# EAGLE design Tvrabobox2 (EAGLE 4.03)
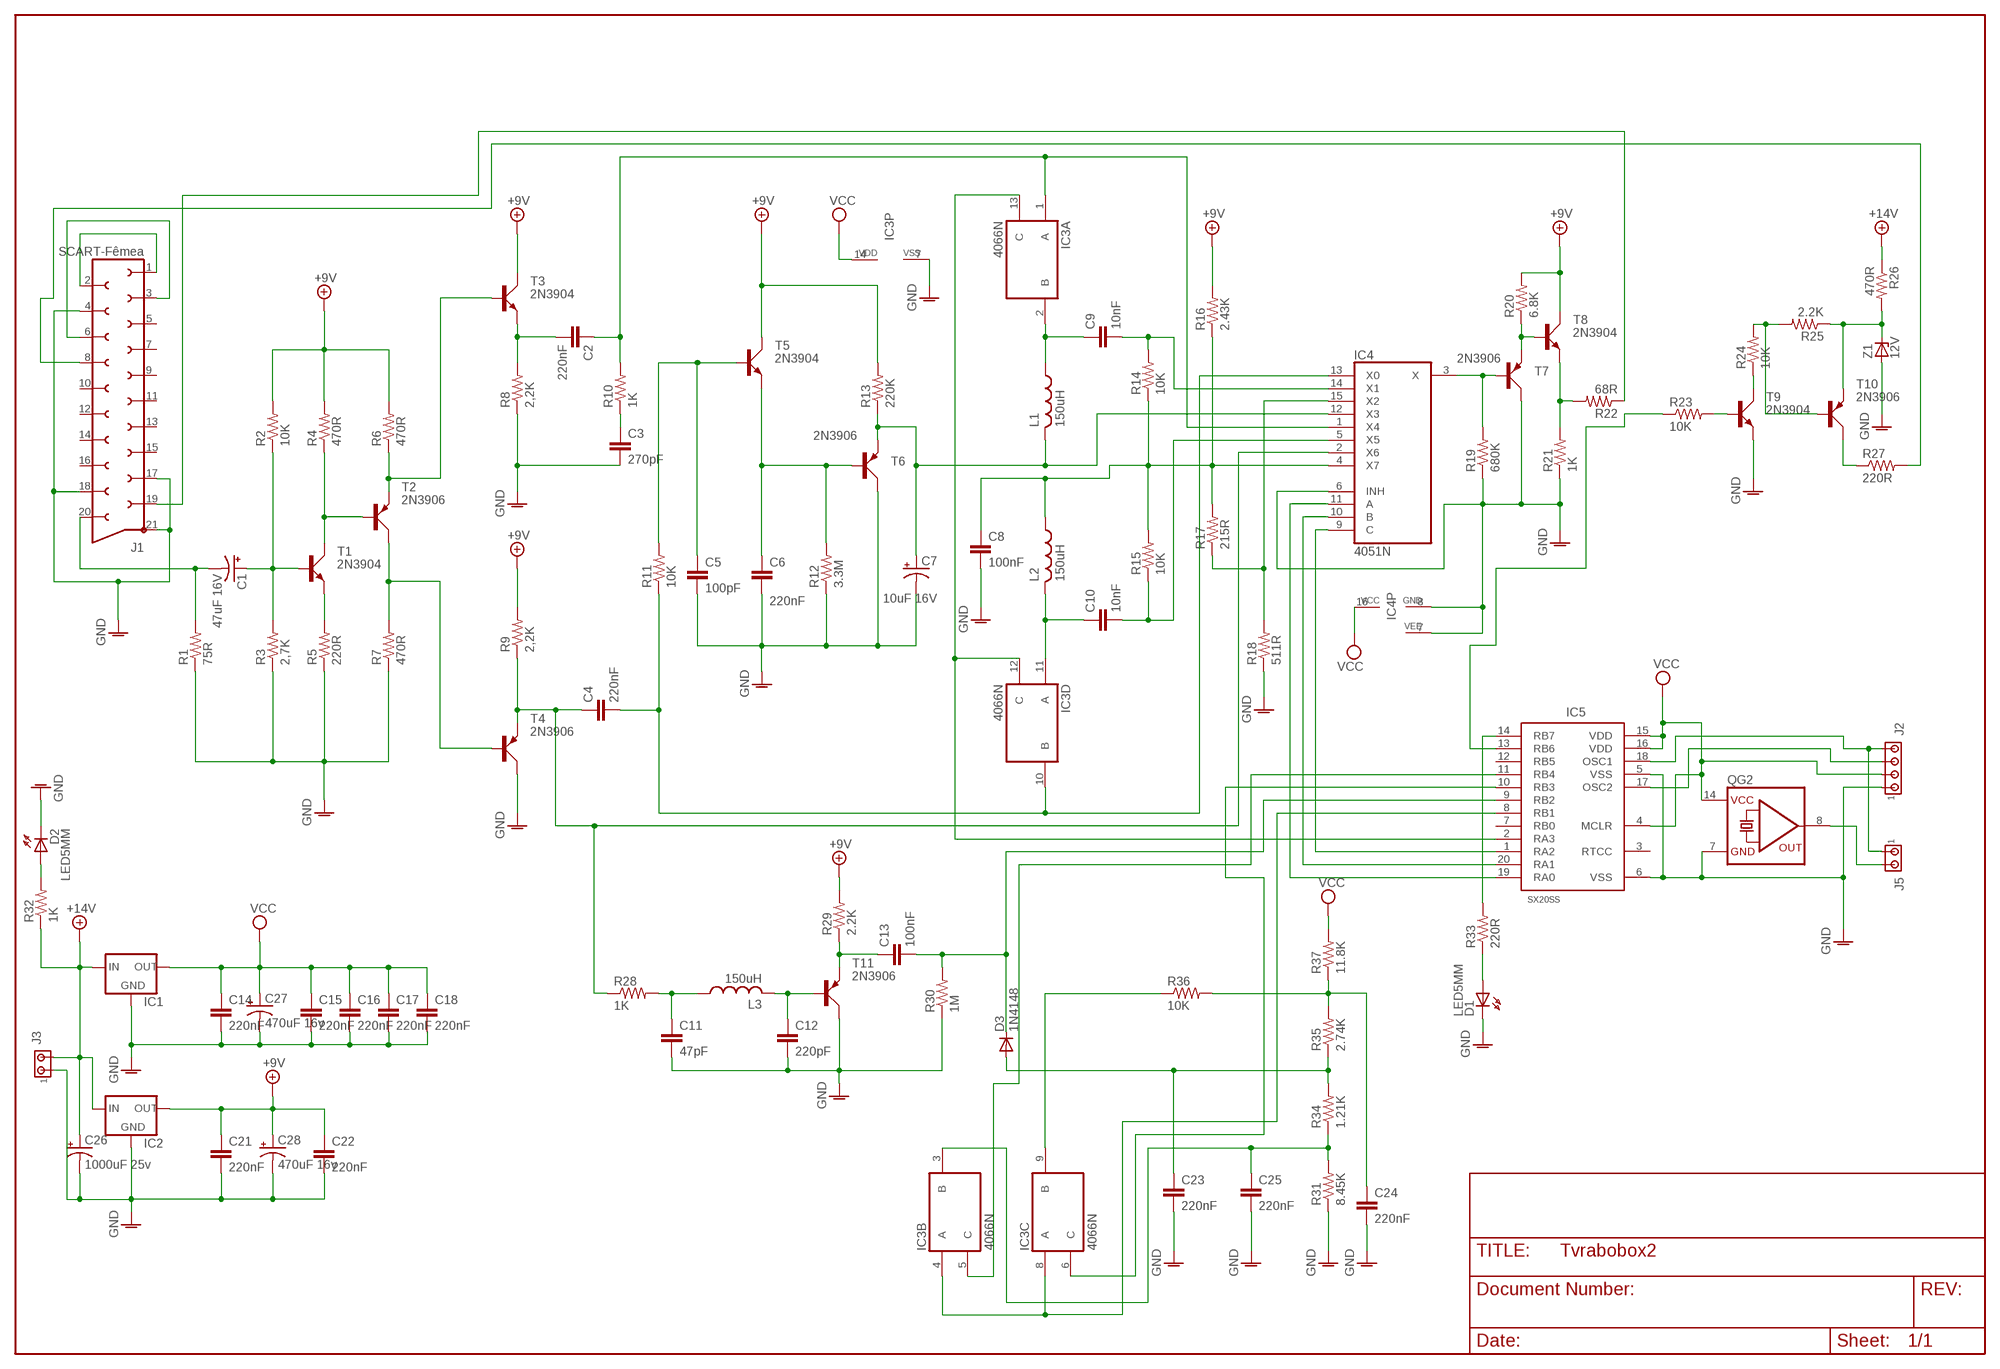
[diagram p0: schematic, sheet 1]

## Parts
C1  47uF 16V  CPOL-USTT2D5  [TT2D5]
C2  220nF  C-EU050-050X075  [C050-050X075]
C3  270pF  C-EU025-025X050  [C025-025X050]
C4  220nF  C-EU050-050X075  [C050-050X075]
C5  100pF  C-EU025-025X050  [C025-025X050]
C6  220nF  C-EU050-050X075  [C050-050X075]
C7  10uF 16V  CPOL-USTT2D5  [TT2D5]
C8  100nF  C-EU025-025X050  [C025-025X050]
C9  10nF  C-EU025-025X050  [C025-025X050]
C10  10nF  C-EU025-025X050  [C025-025X050]
C11  47pF  C-EU025-025X050  [C025-025X050]
C12  220pF  C-EU050-050X075  [C050-050X075]
C13  100nF  C-EU025-025X050  [C025-025X050]
C14  220nF  C-EU050-050X075  [C050-050X075]
C15  220nF  C-EU050-050X075  [C050-050X075]
C16  220nF  C-EU050-050X075  [C050-050X075]
C17  220nF  C-EU050-050X075  [C050-050X075]
C18  220nF  C-EU050-050X075  [C050-050X075]
C21  220nF  C-EU050-050X075  [C050-050X075]
C22  220nF  C-EU050-050X075  [C050-050X075]
C23  220nF  C-EU050-050X075  [C050-050X075]
C24  220nF  C-EU050-050X075  [C050-050X075]
C25  220nF  C-EU050-050X075  [C050-050X075]
C26  1000uF 25v  CPOL-USTT5D10  [TT5D10]
C27  470uF 16v  CPOL-USTT2D7  [TT2D7]
C28  470uF 16v  CPOL-USTT2D7  [TT2D7]
D1  LED5MM  [LED5MM]
D2  LED5MM  [LED5MM]
D3  1N4148  [DO35-10]
IC1  78XXS  [78XXS]
IC2  78XXS  [78XXS]
IC3  4066N  [DIL14]
IC4  4051N  [DIL16]
IC5  SX20AC/SS  [20SSOP]
J1  SCART-Fêmea  SCART-F  [SCART-F]
J2  MTA04-100  [10X04MTA]
J3  MTA02-156  [1X2MTA]
J5  MTA02-100  [10X02MTA]
L1  150uH  L-US0207/10  [0207/10]
L2  150uH  L-US0207/10  [0207/10]
L3  150uH  L-US0207/10  [0207/10]
QG2  QG5860  [DIL14S]
R1  75R  R-US_0207/10  [0207/10]
R2  10K  R-US_0207/10  [0207/10]
R3  2,7K  R-US_0207/10  [0207/10]
R4  470R  R-US_0207/10  [0207/10]
R5  220R  R-US_0207/10  [0207/10]
R6  470R  R-US_0207/10  [0207/10]
R7  470R  R-US_0207/10  [0207/10]
R8  2,2K  R-US_0207/10  [0207/10]
R9  2,2K  R-US_0207/10  [0207/10]
R10  1K  R-US_0207/10  [0207/10]
R11  10K  R-US_0207/10  [0207/10]
R12  3.3M  R-US_0207/10  [0207/10]
R13  220K  R-US_0207/10  [0207/10]
R14  10K  R-US_0207/10  [0207/10]
R15  10K  R-US_0207/10  [0207/10]
R16  2.43K  R-US_0207/10  [0207/10]
R17  215R  R-US_0207/10  [0207/10]
R18  511R  R-US_0207/10  [0207/10]
R19  680K  R-US_0207/10  [0207/10]
R20  6.8K  R-US_0207/10  [0207/10]
R21  1K  R-US_0207/10  [0207/10]
R22  68R  R-US_0207/10  [0207/10]
R23  10K  R-US_0207/10  [0207/10]
R24  10K  R-US_0207/10  [0207/10]
R25  2.2K  R-US_0207/10  [0207/10]
R26  470R  R-US_0207/10  [0207/10]
R27  220R  R-US_0207/10  [0207/10]
R28  1K  R-US_0207/10  [0207/10]
R29  2.2K  R-US_0207/10  [0207/10]
R30  1M  R-US_0207/10  [0207/10]
R31  8.45K  R-US_0207/10  [0207/10]
R32  1K  R-US_0207/10  [0207/10]
R33  220R  R-US_0207/10  [0207/10]
R34  1.21K  R-US_0207/10  [0207/10]
R35  2.74K  R-US_0207/10  [0207/10]
R36  10K  R-US_0207/10  [0207/10]
R37  11.8K  R-US_0207/10  [0207/10]
T1  2N3904  [TO92D]
T2  2N3906  [TO92D]
T3  2N3904  [TO92D]
T4  2N3906  [TO92D]
T5  2N3904  [TO92D]
T6  2N3906  [TO92D]
T7  2N3906  [TO92D]
T8  2N3904  [TO92D]
T9  2N3904  [TO92D]
T10  2N3906  [TO92D]
T11  2N3906  [TO92D]
Z1  12V  BZX55  [DO35Z10]

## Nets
+9V: C21.2 C22.2 C28.+ IC2.OUT R2.2 R4.2 R6.2 R9.2 R13.2 R16.2 R20.2 R29.2 T3.C T5.C T8.C
+14V: C26.+ IC1.IN IC2.IN J3.2 R26.1 R32.1
GNDA: C3.1 C5.1 C6.1 C7.- C8.1 C11.1 C12.1 C14.1 C15.1 C16.1 C17.1 C18.1 C21.1 C22.1 C23.1 C24.1 C25.1 C26.- C27.- C28.- D1.K(C) D2.K(C) IC1.GND IC2.GND IC3.7(P:VSS) IC4.6(INH) IC4.7(VEE) IC4.8(GND) IC5.5(VSS) IC5.6(VSS) J1.4 J1.17 J1.18 J1.21 J2.4 J3.1 QG2.7(GND) R1.1 R3.1 R5.1 R7.1 R8.1 R12.1 R18.1 R19.1 R21.1 R30.1 R31.1 T4.C T6.C T7.C T9.E T11.C Z1.A ; supply symbol labelled GND
N$1: J1.1 J1.2
N$2: J1.3 J1.6
N$3: C4.1 IC3.10(D:B) IC4.13(X0) R11.1
N$4: C3.2 R10.1
N$5: R4.1 T1.C T2.B
N$6: R5.2 T1.E
N$7: C1.+ R2.1 R3.2 T1.B
N$8: C1.- J1.20 R1.2
N$9: C2.1 R8.2 T3.E
N$10: C4.2 IC4.2(X6) R9.1 R28.1 T4.E
N$11: C9.2 IC3.2(A:B) L1.2
N$12: C2.2 IC3.1(A:A) IC4.1(X4) R10.2
N$13: R6.1 T2.E T3.B
N$14: R7.2 T2.C T4.B
N$15: C5.2 R11.2 T5.B
N$16: C6.2 R12.2 T5.E T6.B
N$17: C8.2 IC4.4(X7) L2.2 R14.1 R15.2 R16.1 R17.2
N$18: IC4.15(X2) R17.1 R18.2
N$19: C7.+ IC4.12(X3) L1.1 R13.1 T6.E
N$20: C9.1 IC4.14(X1) R14.2
N$21: IC4.11(A) IC5.19(RA0)
N$22: C10.2 IC3.11(D:A) L2.1
N$23: IC4.10(B) IC5.20(RA1)
N$24: C10.1 IC4.5(X5) R15.1
N$25: IC4.9(C) IC5.1(RA2)
N$26: IC3.12(D:C) IC3.13(A:C) IC5.2(RA3)
N$27: IC4.3(X) R19.2 T7.B
N$28: R20.1 T7.E T8.B
N$29: J1.19 R22.1
N$30: R23.2 T9.B
N$31: R21.2 R22.2 T8.E
N$32: R24.1 T9.C
N$33: R24.2 R25.2 T10.B
N$34: C23.2 D3.A R34.2 R35.1
N$35: R27.1 T10.C
N$36: IC5.13(RB6) R23.1
N$37: J1.8 R27.2
N$38: R25.1 R26.2 T10.E Z1.C
N$39: C24.2 R35.2 R36.2 R37.1
N$41: C25.2 IC3.3(B:B) R31.2 R34.1
N$42: C11.2 L3.2 R28.2
N$43: C12.2 L3.1 T11.B
N$44: C13.2 R29.1 T11.E
N$45: IC3.6(C:C) IC5.10(RB3)
N$46: C13.1 D3.C IC5.9(RB2) R30.2
N$47: D2.A R32.2
N$48: IC3.4(B:A) IC3.8(C:A) IC5.8(RB1)
N$49: IC3.5(B:C) IC5.11(RB4)
N$52: IC5.17(OSC2) J2.2
N$53: IC5.18(OSC1) J2.1 J5.1
N$54: IC3.9(C:B) R36.1
N$55: J5.2 QG2.8(OUT)
N$63: D1.A R33.1
N$64: IC5.14(RB7) R33.2
VCC: C14.2 C15.2 C16.2 C17.2 C18.2 C27.+ IC1.OUT IC3.14(P:VDD) IC4.16(VCC) IC5.4(MCLR) IC5.15(VDD) IC5.16(VDD) J2.3 QG2.14(VCC) R37.2
Unconnected: IC5.3(RTCC) IC5.7(RB0) IC5.12(RB5) J1.5 J1.7 J1.9 J1.10 J1.11 J1.12 J1.13 J1.14 J1.15 J1.16

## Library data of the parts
C1 C7 C26-C28 = rcl:CPOL-US: POLARIZED CAPACITOR, American symbol
C2-C6 C8-C18 C21-C25 = rcl:C-EU: CAPACITOR, European symbol
D1 D2 = led:LED5MM: LED
D3 = diode:1N4148: DIODE
IC1 IC2 = v-reg:78XXS: VOLTAGE REGULATOR
IC3 = 40xx:4066: Quad bilateral ANALOG SWITCH
IC4 = 40xx:4051: 8-channel ANALOG MULTIPLEXER
IC5 = ubicom_v2:SX20AC/SS
J1 = con-hirschmann:SCART-F: TV SCART CONNECTOR
J2 = con-amp:MTA04-100: AMP CONNECTOR
J3 = con-amp:MTA02-156: AMP CONNECTOR
J5 = con-amp:MTA02-100: AMP CONNECTOR
L1-L3 = rcl:L-US: INDUCTOR, American symbol
QG2 = crystal:QG5860: CRYSTAL RESONATOR
R1-R37 = rcl:R-US_: RESISTOR, American symbol
T1 T3 T5 T8 T9 = transistor-small-signal:2N3904: NPN TRANSISTOR
T2 T4 T6 T7 T10 T11 = transistor-small-signal:2N3906: PNP TRANSISTOR
Z1 = diode:BZX55: Z DIODE

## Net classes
0 default: width 0.3 mm

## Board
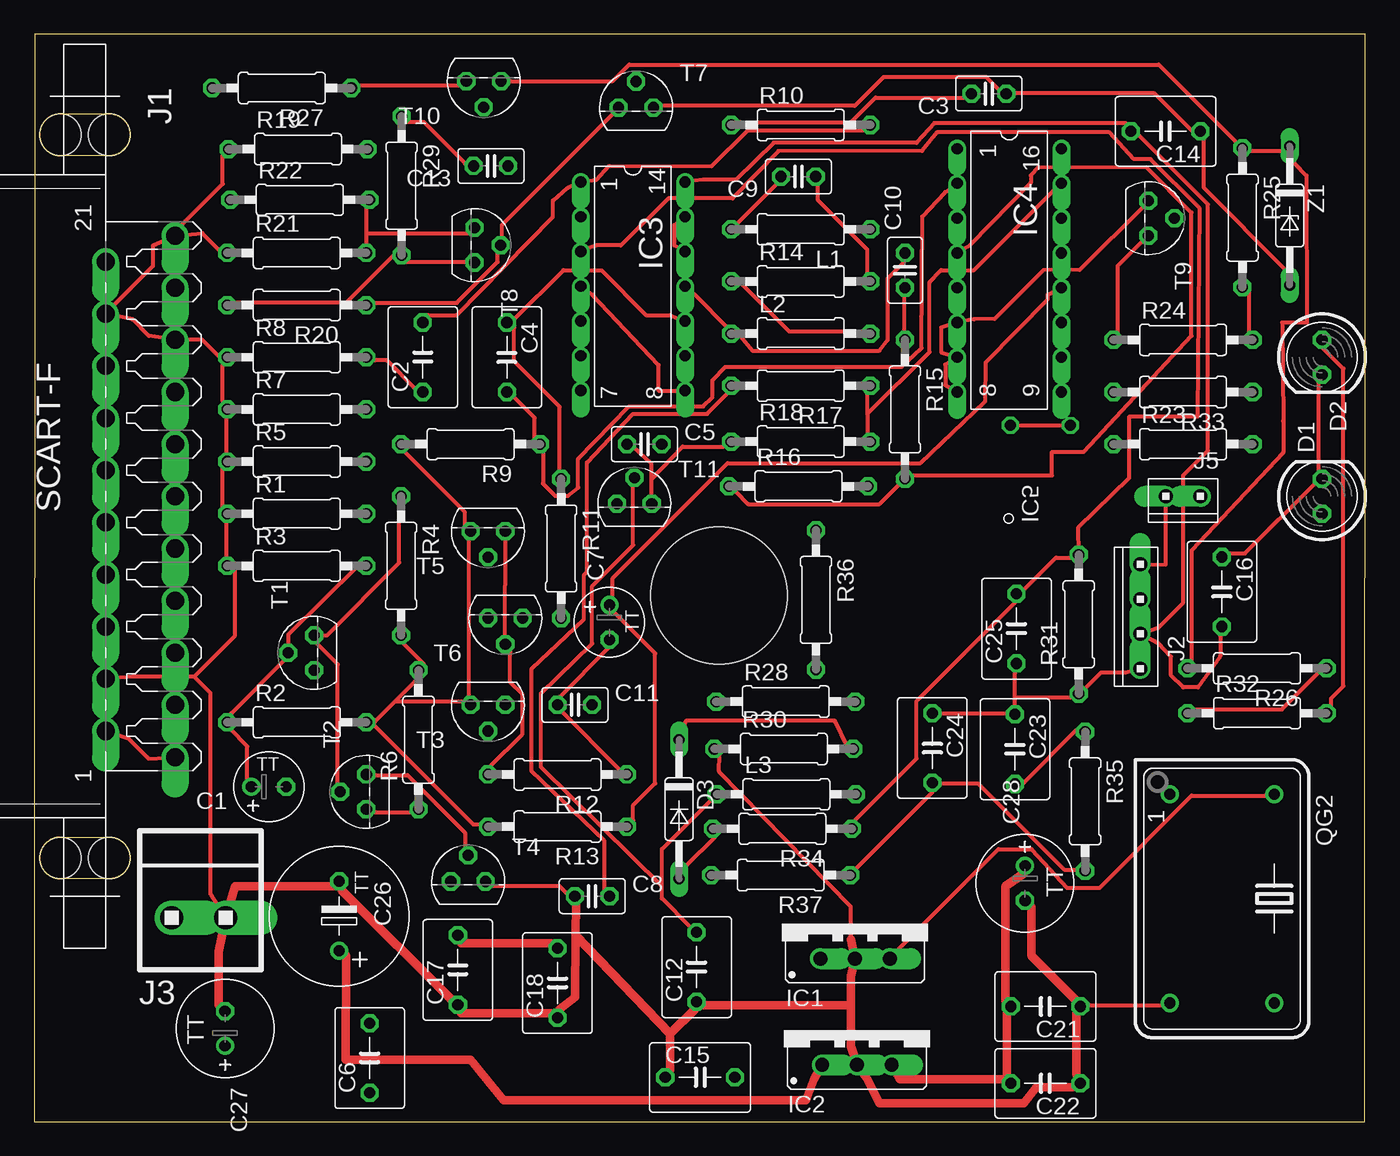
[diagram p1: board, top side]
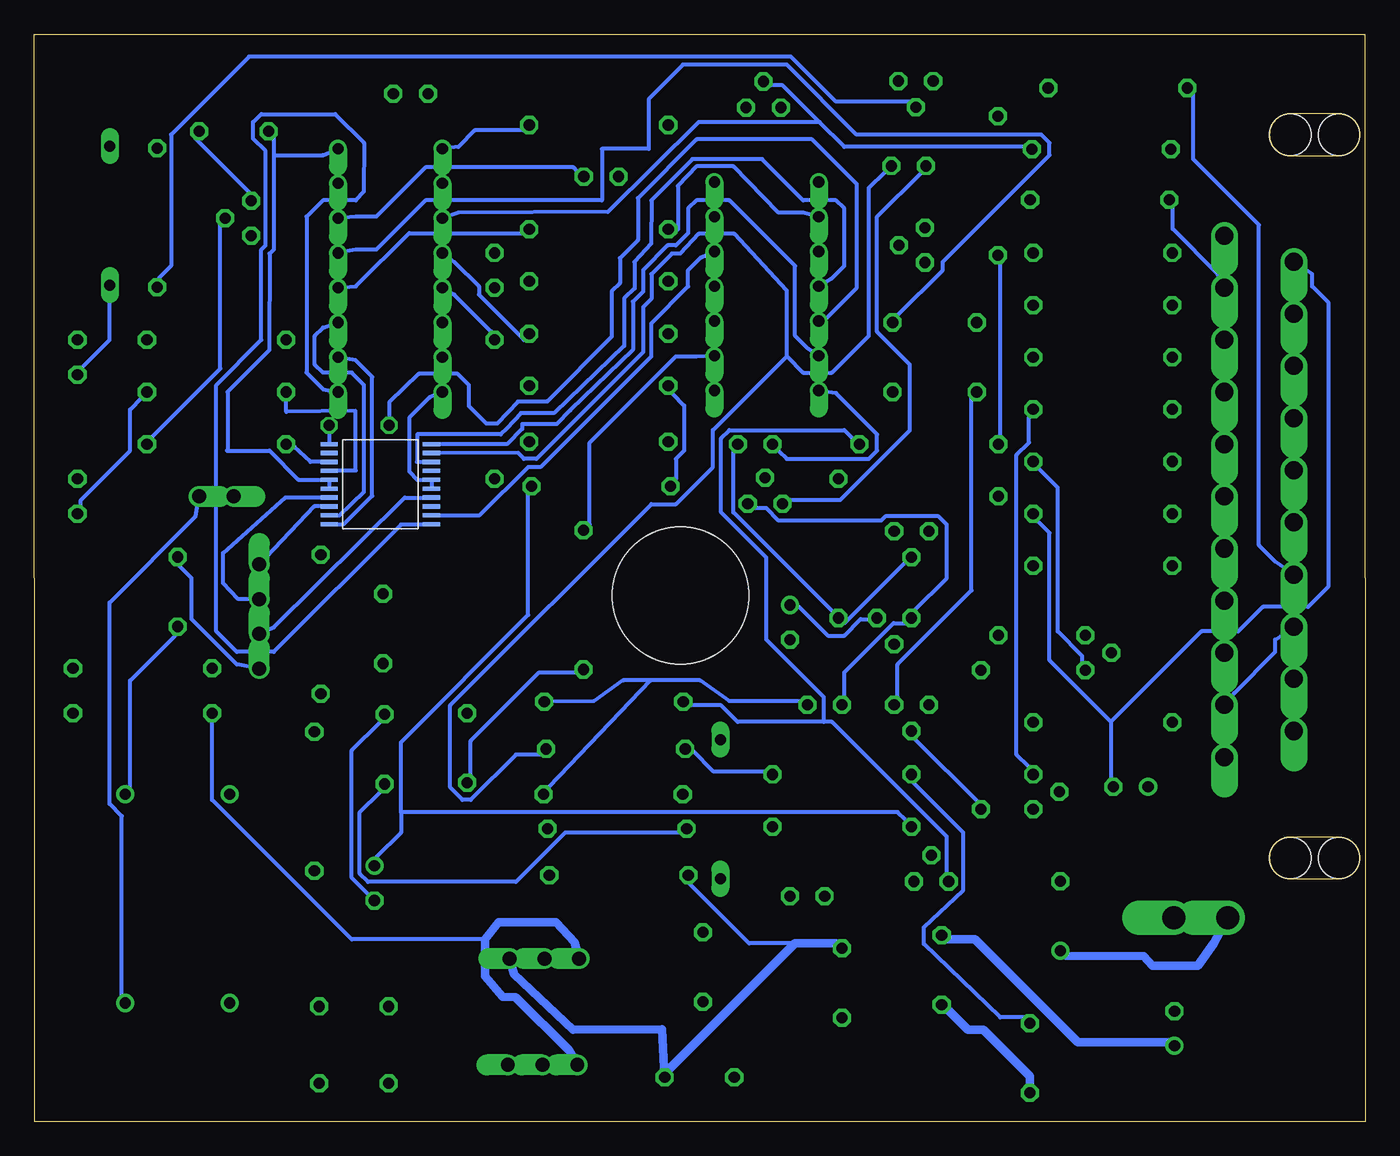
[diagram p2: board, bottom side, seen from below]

Size 97.28 x 79.45 mm. Coordinates in mm from the lower left corner, seen from the top.
Outline: 0,0 97.23,0 97.28,79.45 0.05,79.45 0,0
Copper layers used: Top, Bottom
Holes 10 mm at 50.05,38.45

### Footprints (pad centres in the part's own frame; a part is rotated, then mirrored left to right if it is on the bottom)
TT2D5 = drill 0.813 round: + 1.27,0 | drill 0.813 octagon: - -1.27,0
C050-050X075 = drill 0.813 octagon: 1 -2.54,0; 2 2.54,0
C025-025X050 = drill 0.813 octagon: 1 -1.27,0; 2 1.27,0
TT5D10 = drill 0.813 round: + 2.54,0 | drill 0.813 octagon: - -2.54,0
TT2D7 = drill 0.813 round: + 1.27,0 | drill 0.813 octagon: - -1.27,0
LED5MM = drill 0.813 octagon: A -1.27,0; K 1.27,0
DO35-10 = drill 0.813 long: A 5.08,0; C -5.08,0
78XXS = drill 1.016 offset: GND 0,-2.54; IN -2.54,-2.54; OUT 2.54,-2.54
DIL14 = drill 0.813 offset: 1 -7.62,-3.81; 2 -5.08,-3.81; 3 -2.54,-3.81; 4 0,-3.81; 5 2.54,-3.81; 6 5.08,-3.81; 7 7.62,-3.81; 8 7.62,3.81; 9 5.08,3.81; 10 2.54,3.81; 11 0,3.81; 12 -2.54,3.81; 13 -5.08,3.81; 14 -7.62,3.81
DIL16 = drill 0.813 offset: 1 -8.89,-3.81; 2 -6.35,-3.81; 3 -3.81,-3.81; 4 -1.27,-3.81; 5 1.27,-3.81; 6 3.81,-3.81; 7 6.35,-3.81; 8 8.89,-3.81; 9 8.89,3.81; 10 6.35,3.81; 11 3.81,3.81; 12 1.27,3.81; 13 -1.27,3.81; 14 -3.81,3.81; 15 -6.35,3.81; 16 -8.89,3.81
20SSOP = smd 0.305 x 1.27: 1 -3.901,-3.901; 2 -3.251,-3.901; 3 -2.601,-3.901; 4 -1.951,-3.901; 5 -1.3,-3.901; 6 -0.65,-3.901; 7 0,-3.901; 8 0.65,-3.902; 9 1.3,-3.901; 10 1.951,-3.901; 11 1.951,3.576; 12 1.3,3.576; 13 0.65,3.576; 14 0,3.576; 15 -0.65,3.576; 16 -1.3,3.576; 17 -1.951,3.576; 18 -2.601,3.576; 19 -3.251,3.576; 20 -3.901,3.576
SCART-F = drill 1.321 offset: 1 19.05,5.08; 2 17.145,0; 3 15.24,5.08; 4 13.335,0; 5 11.43,5.08; 6 9.525,0; 7 7.62,5.08; 8 5.715,0; 9 3.81,5.08; 10 1.905,0; 11 0,5.08; 12 -1.905,0; 13 -3.81,5.08; 14 -5.715,0; 15 -7.62,5.08; 16 -9.525,0; 17 -11.43,5.08; 18 -13.335,0; 19 -15.24,5.08; 20 -17.145,0; 21 -19.05,5.08 | hole 3.023: 26.416,0.254; 26.416,-3.302; -26.416,0.254; -26.416,-3.302
10X04MTA = drill 1.016 offset: 1 3.81,0; 2 1.27,0; 3 -1.27,0; 4 -3.81,0
1X2MTA = drill 1.676 offset: 1 1.981,0; 2 -1.981,0
10X02MTA = drill 1.016 offset: 1 1.27,0; 2 -1.27,0
0207/10 = drill 0.813 octagon: 1 -5.08,0; 2 5.08,0
DIL14S = drill 0.813 round: 1 -7.62,-3.81; 7 7.62,-3.81; 8 7.62,3.81; 14 -7.62,3.81
TO92D = drill 0.813 octagon: B 0,1.905; C 1.27,0; E -1.27,0
DO35Z10 = drill 0.813 long: A 5.08,0; C -5.08,0

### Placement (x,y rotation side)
C1  17.15,24.47 180 top
C2  28.4,55.85 90 top
C3  69.77,75.11 180 top
C4  34.54,55.85 270 top
C5  44.59,49.5 0 top
C6  24.52,4.65 90 top
C7  42.03,36.48 90 top
C8  40.78,16.48 0 top
C9  55.84,69.05 180 top
C10  63.64,62.2 90 top
C11  39.51,30.45 0 top
C12  48.42,11.3 90 top
C13  33.37,69.83 180 top
C14  82.69,72.36 180 top
C15  48.66,3.24 0 top
C16  86.8,38.72 270 top
C17  30.96,11.09 90 top
C18  38.24,10.13 90 top
C21  73.91,8.42 180 top
C22  73.91,2.8 180 top
C23  71.68,27.22 270 top
C24  65.64,27.31 270 top
C25  71.79,36.02 90 top
C26  22.29,15.02 270 top
C27  13.94,6.81 270 top
C28  72.42,17.43 90 top
D1  94.12,45.69 90 top
D2  94.12,55.85 270 top
D3  47.13,22.83 270 top
IC1  59.99,14.46 0 top
IC2  60.13,6.7 0 top
IC3  43.75,61.04 270 top
IC4  71.26,62.2 270 top
IC5  72.15,47.55 90 bottom
J1  5.22,45.69 270 top
J2  80.84,36.91 90 top
J3  12.02,14.91 0 top
J5  83.96,45.69 180 top
L1  56.02,65.2 180 top
L2  56.02,57.58 0 top
L3  54.96,23.92 0 top
QG2  86.81,16.3 270 top
R1  19.19,44.42 0 top
R2  19.19,29.18 0 top
R3  19.19,40.61 0 top
R4  26.81,40.61 270 top
R5  19.19,48.23 0 top
R6  28.08,27.91 90 top
R7  19.19,52.04 0 top
R8  19.19,55.85 0 top
R9  31.89,49.5 180 top
R10  56.02,72.82 0 top
R11  38.51,41.88 270 top
R12  38.24,25.37 180 top
R13  38.24,21.56 180 top
R14  56.02,61.39 0 top
R15  63.64,52.04 270 top
R16  55.85,46.42 0 top
R17  56.02,53.77 180 top
R18  56.02,49.69 0 top
R19  19.28,71.06 0 top
R20  19.19,59.66 180 top
R21  19.19,63.47 0 top
R22  19.41,67.36 0 top
R23  83.96,49.5 0 top
R24  83.96,57.12 0 top
R25  88.3,66.05 270 top
R26  89.37,33.13 180 top
R27  18.1,75.52 180 top
R28  54.92,30.69 0 top
R29  26.85,68.38 270 top
R30  54.78,27.24 0 top
R31  76.33,36.35 90 top
R32  89.37,29.85 0 top
R33  83.96,53.31 180 top
R34  54.67,21.41 180 top
R35  76.81,23.41 270 top
R36  57.13,38.12 270 top
R37  54.56,18.02 180 top
T1  20.46,34.26 90 top
T2  24.27,24.1 90 top
T3  33.16,30.45 180 top
T4  31.72,17.55 0 top
T5  33.16,43.15 180 top
T6  34.43,36.8 180 top
T7  43.99,74.09 0 top
T8  32.18,64.04 270 top
T9  81.42,66.01 270 top
T10  32.85,76.03 180 top
T11  43.86,45.15 0 top
Z1  91.76,66.2 270 top

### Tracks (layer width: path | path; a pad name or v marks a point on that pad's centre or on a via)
+9V
  Top 0.3: C22.2 70.78,3.12 | R20.2 14.68,59.82 22.78,59.82 26.38,63.42 R29.2 27.28,62.82 31.78,62.82 T8.C | R9.2 26.98,49.02 31.48,44.52 31.48,43.62 T5.C 31.78,42.72 31.78,31.02 T3.C 31.48,30.72 26.38,30.72 | 26.38,30.72 28.18,32.52 R6.2 28.48,33.42 26.98,34.92 R4.2 | 26.38,30.72 24.88,29.22 R2.2 24.88,28.92 32.08,21.72 32.68,21.72 R13.2
  Top 0.61: C22.2 71.08,3.42 71.08,7.92 C21.2 70.97,8.82 70.97,17.22 72.28,18.12 C28.+ | 70.78,3.12 63.28,3.12 IC2.OUT
  Bottom 0.3: 70.48,22.62 70.48,21.12 72.28,19.32 C28.+ | 70.48,22.62 70.48,27.72 61.18,37.02 61.18,46.02 R16.2 | R29.2 26.68,62.82 26.68,49.92 R9.2 | 70.48,22.62 34.18,22.62 33.58,22.02 R13.2
+14V
  Top 0.3: R32.1 84.88,30.12 91.18,30.12 93.88,32.82 R26.1
  Top 0.61: C26.+ 22.78,12.12 22.75,4.54 31.9,4.53 34.3,1.57 56.41,1.57 56.98,3.12 IC2.IN
  Bottom 0.3: 21.88,12.12 C26.+ | 64.35,13.32 74.08,13.32 84.28,23.52 84.28,29.22 R32.1
  Bottom 0.61: 21.88,12.12 16.17,12.1 15.56,11.38 12.26,11.38 11.08,13.02 J3.2 | IC2.IN 58.18,5.22 62.1,9.11 63.05,9.13 64.35,10.62 64.35,13.32 63.36,14.57 59.16,14.57 57.8,13.12 IC1.IN
GNDA
  Top 0.3: T7.C 45.88,74.22 59.98,74.22 62.08,76.32 69.58,76.32 70.48,75.42 C3.1 71.68,75.12 81.88,75.12 84.58,72.42 C14.1 85.48,71.82 85.48,68.22 91.48,62.22 Z1.A | 76.18,8.82 C21.1 77.08,8.52 82.48,8.52 QG2.7 | 71.68,31.02 71.68,32.82 C25.1 | 71.68,31.02 71.68,30.12 C23.1 71.08,29.82 66.28,29.82 C24.1 | 71.68,31.02 75.88,31.02 R31.1 76.78,31.62 77.98,32.82 79.78,32.82 J2.4 | IC4.8 66.58,53.82 66.58,55.32 IC4.7 66.28,56.22 66.28,58.02 IC4.6 68.68,58.62 70.2,58.65 73.77,62.22 76.42,62.23 81.16,66.97 T9.E | C16.1 87.28,41.52 88.48,41.52 93.58,46.62 D1.K 93.88,47.52 93.88,54.12 D2.K | 11.68,32.52 7.18,32.52 J1.4 | 11.68,32.52 14.68,35.52 14.68,40.32 R3.1 14.08,41.22 14.08,43.92 R1.1 13.78,44.82 13.78,47.82 R5.1 14.08,48.72 14.08,51.42 R7.1 13.78,52.62 13.78,55.32 R8.1 13.48,55.92 12.28,57.12 J1.17 8.38,57.42 7.18,58.62 J1.18 5.98,59.82 8.68,62.52 8.68,64.02 J1.21 | R21.1 13.48,63.72 12.28,64.92 J1.21 | R19.1 13.78,70.62 13.78,68.52 10.78,65.52 J1.21 | 45.11,46.92 45.11,48.08 43.78,49.32 C5.1 | 45.11,46.92 45.11,45.72 T11.C | 45.11,46.92 47.38,49.32 50.38,49.32 R18.1 | C7.- 41.98,34.62 38.38,31.02 C11.1 38.38,30.12 42.88,25.62 R12.1 | C27.- 13.48,8.52 | 21.88,17.22 C26.- | T4.C 33.58,17.22 38.38,17.22 38.98,16.62 C8.1 | 59.68,13.32 59.68,15.72 50.06,25.58 50.08,26.82 R30.1 | 11.68,32.52 12.88,31.32 12.88,16.62 J3.1
  Top 0.61: 76.18,8.82 72.88,12.12 72.88,15.72 C28.- | C21.1 76.18,7.92 76.18,3.42 C22.1 75.88,2.52 73.23,2.52 72.33,1.34 61.78,1.36 60.88,3.12 IC2.GND 59.68,5.52 59.68,8.52 | 13.48,8.52 13.48,12.42 J3.1 14.68,17.22 21.88,17.22 | 59.68,8.52 59.68,10.62 IC1.GND 59.68,13.32 | 46.48,6.42 46.48,3.72 C15.1 | 46.48,6.42 48.28,8.22 C12.1 48.88,8.52 59.68,8.52 | 39.58,13.62 39.53,9.1 38.38,8.22 C18.1 37.78,7.92 31.18,7.92 C17.1 30.58,8.82 22.48,16.92 C26.- | 39.58,13.62 39.59,15.97 C8.1 | 39.58,13.62 46.48,6.42
  Bottom 0.3: IC5.5 68.25,46.29 IC5.6 68.68,46.9 69.28,46.9 69.88,47.52 69.88,51.42 68.38,52.92 IC4.8 | T9.E 81.58,67.92 85.48,71.82 C14.1 | Z1.A 91.78,59.82 91.78,57.12 93.88,55.02 D2.K | J2.4 82.48,33.42 85.78,36.72 85.78,39.72 86.68,40.62 C16.1 | C28.- 72.88,16.62 74.08,17.82 74.08,27.12 71.98,29.22 C23.1 | IC3.7 38.68,53.22 35.68,50.22 35.68,49.02 36.28,48.42 42.28,48.42 42.88,49.02 C5.1 | C11.1 38.08,31.02 38.08,32.82 34.48,36.42 33.58,36.42 T6.C 32.98,37.32 30.58,39.72 30.58,43.62 31.18,44.22 35.08,44.22 35.38,43.92 42.88,43.92 43.78,44.82 44.68,44.82 T11.C | R30.1 49.18,27.12 47.68,25.62 43.78,25.62 R12.1
  Bottom 0.406: C17.1 30.91,8.6
  Bottom 0.61: C6.1 24.52,3.33 27.91,6.72 29.03,6.72 30.91,8.6
N$1
  Top 0.3: J1.2 6.88,28.02 8.38,26.52 J1.1
N$2
  Bottom 0.3: J1.6 6.58,35.22 6.58,34.32 9.58,31.32 J1.3
N$3
  Top 0.3: R11.1 38.38,47.52 38.4,52.23 35.08,55.56 35.08,58.02 C4.1 35.08,58.62 38.68,62.22 41.48,62.2 44.7,58.92 46.48,58.92 IC3.10
  Bottom 0.3: IC4.13 73.78,63.72 72.28,63.72 68.68,67.32 55.78,67.31 55.78,71.08 52.38,71.08 52.38,74.7 49.87,77.22 42.28,77.22 37.18,72.12 23.68,72.12 23.08,71.52 23.08,70.62 30.88,62.82 30.88,62.22 34.18,58.92 C4.1
N$4
  Top 0.3: R10.1 51.58,73.02 59.68,73.02 61.48,74.82 68.08,74.82 C3.2
N$5
  Top 0.3: T2.B 22.18,24.72 22.18,33.42 20.68,34.92 T1.C 21.39,35.54 26.68,40.85 26.68,45.12 R4.1
N$6
  Bottom 0.3: T1.E 20.68,33.42 20.68,34.02 22.48,35.82 22.48,46.32 23.98,47.82 R5.2
N$7
  Top 0.3: C1.+ 15.58,25.02 15.58,27.42 14.38,28.62 R2.1 14.38,29.82 18.28,33.72 T1.B 18.58,34.92 18.58,35.61 23.68,40.63 R3.2
N$8
  Bottom 0.3: 18.58,29.22 18.58,25.02 C1.- | 18.58,29.22 23.08,33.72 23.08,43.02 23.98,43.92 R1.2 | 18.58,29.22 11.98,35.82 9.28,35.82 7.48,37.62 4.18,37.62 2.68,39.12 2.68,59.82 3.88,61.02 3.88,61.92 J1.20
N$9
  Top 0.3: R8.2 24.88,55.62 25.78,55.62 27.88,53.52 C2.1
  Bottom 0.3: T3.E 34.18,31.02 34.18,33.42 28.78,38.82 28.78,52.92 C2.1
N$10
  Top 0.3: C4.2 35.08,52.92 36.58,51.42 36.58,49.92 R9.1 37.18,49.02 37.18,46.62 38.08,45.72 38.98,45.72 39.76,46.32 39.76,48.42 43.48,52.27 48.88,52.27 49.57,52.92 49.57,54.17 50.52,55.14 63.38,55.15 64.85,56.52 64.91,66.12 66.58,67.92 IC4.2
  Bottom 0.3: 39.58,29.22 45.88,29.22 47.08,30.42 49.48,30.42 R28.1 | 39.58,29.22 38.98,29.22 30.58,20.82 30.58,18.12 T4.E | 39.58,29.22 39.58,31.02 43.78,35.22 43.78,41.22 47.08,44.52 47.08,49.92 46.48,50.52 38.08,50.52 37.48,49.92 R9.1
N$11
  Top 0.3: L1.2 51.28,65.52 54.28,68.52 C9.2
  Bottom 0.3: IC3.2 41.08,66.42 42.88,66.42 46.18,69.8 48.88,69.8 50.24,68.38 50.24,65.18 L1.2
N$12
  Top 0.3: C2.2 28.78,58.92 30.88,58.92 37.91,66.11 37.91,67.29 38.98,68.22 IC3.1 41.08,68.82 42.02,69.83 49.48,69.81 52.18,72.42 60.58,72.42 R10.2
  Bottom 0.3: R10.2 61.48,72.42 65.08,72.42 66.28,71.22 IC4.1
N$13
  Top 0.3: T2.E 24.88,22.62 27.58,22.62 R6.1
  Bottom 0.3: T3.B 32.98,28.02 28.18,23.22 R6.1
N$14
  Top 0.3: T2.C 24.88,25.32 27.28,25.32 31.48,21.12 31.48,19.92 T4.B
  Bottom 0.3: R7.2 24.58,51.42 24.58,49.62 25.48,48.72 25.48,26.82 24.58,25.92 T2.C
N$15
  Bottom 0.3: T5.B 33.58,40.92 38.08,36.42 R11.2 38.68,37.02 46.18,44.52 46.18,49.02 C5.2
N$16
  Top 0.3: T5.E 34.43,42.78 34.4,35.58 T6.B 34.78,34.32 34.78,32.12 35.68,31.22 35.68,28.32 33.28,25.92 R12.2
  Bottom 0.3: C6.2 24.88,7.62 26.68,7.62 32.26,13 32.26,14.2 29.38,16.92 29.38,21.12 32.98,24.72 R12.2
N$17
  Top 0.3: L2.2 60.58,57.72 55.18,57.72 51.58,61.32 R14.1 | C8.2 41.68,16.92 41.68,20.52 36.37,25.6 36.37,33.1 40.18,36.72 40.19,39.97 40.39,40.19 40.39,48.15 43.78,51.72 49.18,51.72 50.68,53.22 R17.2 | R16.1 51.28,46.02 52.18,45.12 61.78,45.12 63.28,46.62 R15.2 64.18,47.22 74.38,47.22 74.38,48.94 76.7,48.93 84.58,57.42 84.58,66.42 81.28,69.72 73.37,69.7 72.83,69.15 72.83,68.61 68.38,64.02 IC4.4
  Bottom 0.3: IC4.4 66.58,62.82 64.78,61.02 64.78,60.42 61.48,57.12 L2.2 | R16.1 50.38,46.92 50.38,48.42 49.78,49.02 49.78,52.32 50.68,53.22 R17.2
N$18
  Top 0.3: 60.88,51.72 60.88,53.22 R17.1 | 60.88,51.72 60.88,50.22 R18.2 | 60.88,51.72 65.44,56.22 65.44,61.32 66.28,62.22 68.68,62.22 74.38,67.92 IC4.15
N$19
  Top 0.3: R13.1 43.78,22.02 43.78,23.12 45.38,24.72 45.38,34.22 42.28,37.32 C7.+ 42.28,38.22 42.28,39.72 50.68,48.12 64.78,48.12 69.51,52.62 69.54,55.49 74.08,60.1 74.08,60.42 IC4.12
  Bottom 0.3: L1.1 61.48,64.92 69.88,64.92 73.78,61.02 IC4.12 | T6.E 36.28,36.72 36.88,36.72 38.08,35.52 39.28,35.52 41.38,37.62 C7.+
N$20
  Top 0.3: R14.2 60.88,61.92 60.88,63.72 57.28,67.32 57.28,68.52 C9.1
  Bottom 0.3: IC4.14 73.78,66.12 72.28,66.12 68.68,69.72 57.88,69.72 57.58,69.42 C9.1
N$21
  Bottom 0.3: IC5.19 75.28,44.29 74.96,44.3 73.18,46.02 73.18,53.82 74.08,54.72 76.18,54.72 76.78,55.32 76.78,57.42 76.18,58.02 IC4.11
N$22
  Top 0.3: IC3.11 48.28,60.42 50.68,58.02 L2.1 51.58,57.42 52.48,56.34 61.78,56.34 62.38,57.12 62.38,61.62 63.58,62.82 C10.2
N$23
  Bottom 0.3: IC5.20 75.28,43.66 74.68,43.66 72.58,45.72 72.58,54.42 73.78,55.62 IC4.10
N$24
  Top 0.3: R15.1 63.58,57.72 63.58,60.42 C10.1
  Bottom 0.3: IC4.5 66.58,60.42 63.88,57.72 R15.1
N$25
  Bottom 0.3: IC5.1 68.68,43.62 70.48,43.62 79.78,34.32 82.48,34.32 83.98,35.82 83.98,53.82 80.68,57.12 80.68,63.72 80.38,64.02 80.38,70.92 81.28,71.82 81.28,73.02 80.68,73.62 75.28,73.62 73.18,71.52 73.21,67.96 73.78,67.32 76.18,67.32 77.38,66.12 77.38,54.72 76.18,53.52 IC4.9
N$26
  Top 0.3: IC3.13 46.78,65.52 46.78,64.02 IC3.12
  Bottom 0.3: IC5.2 67.79,44.29 64.78,44.27 61.18,47.82 60.28,47.82 52.18,55.92 52.18,58.32 49.48,61.02 49.48,62.22 48.58,63.12 IC3.12
N$27
  Bottom 0.3: 39.88,73.02 42.58,75.72 43.48,75.72 T7.B | 39.88,73.02 38.08,71.22 24.88,71.22 R19.2 | 39.88,73.02 48.73,73.02 55.36,66.48 66.28,66.42 IC4.3
N$28
  Top 0.3: R20.1 24.88,59.82 30.88,59.82 33.88,62.82 33.88,63.42 T8.B 34.18,64.62 34.18,65.52 42.28,73.62 T7.E
N$29
  Bottom 0.3: R22.1 14.08,66.72 14.08,65.22 10.78,61.92 J1.19
N$30
  Bottom 0.3: T9.B 83.68,65.52 83.68,55.02 88.78,49.92 R23.2
N$31
  Top 0.3: 24.28,64.92 24.28,66.72 R22.2 | 24.28,64.92 24.28,64.02 R21.2 | 24.28,64.92 31.78,64.92 T8.E
N$32
  Top 0.3: R24.1 79.18,57.72 79.18,62.52 80.98,64.32 T9.C
N$33
  Top 0.3: R24.2 88.78,57.72 88.78,60.72 R25.2
  Bottom 0.3: T10.B 33.28,74.52 38.68,74.52 41.98,77.82 81.58,77.82 87.28,72.12 87.28,62.52 88.18,61.62 R25.2
N$34
  Top 0.3: D3.A 47.68,18.72 49.78,20.82 R34.2 | C23.2 72.28,24.72 76.18,28.62 R35.1
  Bottom 0.3: R34.2 50.08,21.12 58.48,21.12 62.08,17.52 72.88,17.52 73.48,18.12 73.48,22.62 71.98,24.12 C23.2
N$35
  Top 0.3: R27.1 23.68,75.72 31.18,75.72 T10.C
N$36
  Bottom 0.3: IC5.13 76.24,48.21 77.09,48.21 78.28,49.32 R23.1
N$37
  Bottom 0.3: R27.2 12.58,75.12 12.58,70.32 7.78,65.52 7.78,42.12 6.58,40.92 J1.8
N$38
  Top 0.3: R26.2 84.58,33.72 84.58,41.72 91.28,48.89 91.27,51.19 91.2,58.38 93.02,58.38 92.98,69.12 92.08,70.02 Z1.C 91.18,70.92 88.78,70.92 R25.1 87.88,71.52 82.18,77.22 43.48,77.22 42.28,76.02 34.78,76.02 T10.E
N$39
  Top 0.3: R37.1 59.98,18.42 65.68,24.12 C24.2 66.28,24.72 68.98,24.72 75.28,18.42 76.18,18.42 R35.2
  Bottom 0.3: R36.2 57.58,32.82 60.38,32.82 65.38,27.82 65.38,25.32 C24.2
N$41
  Top 0.3: R34.1 59.98,22.02 64.48,26.52 64.48,30.72 71.68,37.92 C25.2 72.28,38.82 74.68,41.22 75.88,41.22 R31.2 76.33,43.44 80.04,47.03 80.04,51.52 85.04,51.52 85.18,66.72 81.58,70.32 80.38,70.32 78.58,72.28 65.98,72.28 64.88,70.92 54.38,70.9 51.04,67.45 46.36,67.46 42.88,64.02 41.08,64.02 IC3.3
N$42
  Bottom 0.3: 52.23,32.24 54.25,32.24 56.38,30.72 R28.2 | 52.23,32.24 48.62,32.24 46.48,30.72 41.38,30.72 C11.2 | 52.23,32.24 59.68,24.42 L3.2
N$43
  Top 0.3: 45.88,17.22 45.88,19.92 49.48,23.52 L3.1 | 45.88,17.22 45.88,16.32 47.98,14.22 C12.2 | 45.88,17.22 37.04,25.9 37.04,31.3 40.78,34.92 40.78,39.12 43.78,42.12 43.78,46.62 T11.B
N$44
  Top 0.3: R29.1 27.28,73.02 28.48,73.02 31.48,70.02 C13.2
  Bottom 0.3: T11.E 41.98,45.42 38.38,45.42 33.28,50.52 33.28,55.32 35.68,57.72 35.68,66.12 32.38,69.42 C13.2
N$45
  Bottom 0.3: IC5.10 62.73,49.51 61.61,50.63 61.61,50.97 59.09,50.96 58.11,51.98 53.53,56.39 53.53,59.91 52.78,60.65 52.78,62.22 50.98,64.02 50.38,64.02 49.48,64.92 49.48,66.72 48.88,67.32 46.48,67.32 41.68,62.52 41.68,57.42 40.78,56.52 IC3.6
N$46
  Top 0.3: D3.C 47.68,29.32 58.48,29.32 59.38,27.42 R30.2
  Bottom 0.3: 42.28,55.92 42.28,60.72 46.12,64.86 48.72,64.86 50.08,63.42 50.68,63.42 52.18,61.92 52.18,60.12 52.78,59.52 52.78,56.22 60.58,48.42 61.48,48.42 61.9,48.86 67.62,48.85 IC5.9 | 42.28,55.92 41.08,54.72 38.98,54.72 36.28,57.42 36.28,68.22 35.08,69.42 C13.1 | 42.28,55.92 47.68,50.52 47.68,47.82 50.38,45.12 52.18,45.12 66.88,30.42 66.88,24.42 65.98,23.52 65.38,23.52 62.08,26.82 60.28,26.82 R30.2
N$47
  Top 0.3: R32.2 94.78,30.42 94.78,30.92 95.68,31.82 95.68,55.02 94.18,56.52 D2.A
N$48
  Top 0.3: IC3.8 45.64,53.41 45.64,55.28 40.78,60.42 IC3.4
  Bottom 0.3: IC5.8 68.7,48.21 69.3,48.21 69.28,50.22 63.19,50.22 62.77,50.61 61.71,51.77 59.29,51.77 54.16,56.69 54.17,60.15 53.41,60.88 53.41,62.81 52.19,64.15 52.18,67.32 49.18,70.32 44.08,70.32 41.08,67.32 38.68,67.32 38.08,66.72 38.08,62.52 38.98,61.62 IC3.4
N$49  (via drill 0.81, 0.81 pad 0.81)
  Top 0.305: v71.34,50.88 v75.72,50.88 v75.73,50.88
  Bottom 0.305: IC3.5 39.61,58.5 37.16,60.95 37.16,68.5 40.43,71.77 48.88,71.77 53.16,67.49 53.16,64.41 54.47,63.1 54.47,61.26 55.07,60.66 55.07,57.35 59.77,52.66 59.77,52.61 60.39,52.61 61.93,52.61 63.44,51 64.23,51 65.51,52.28 65.51,53.81 66.34,54.64 69.18,54.64 71.34,52.55 v71.34,50.88 | IC5.11 v75.73,50.87 v75.73,50.88
N$52
  Bottom 0.3: IC5.17 76.21,45.61 78.91,45.62 83.47,41.54 83.47,39.35 82.37,38.18 J2.2
N$53
  Top 0.3: J5.1 82.7,44.24 82.7,40.7 J2.1
  Bottom 0.3: IC5.18 76.21,44.95 76.81,44.95 80.38,41.22 J2.1
N$54
  Bottom 0.3: IC3.9 48.88,55.92 50.38,55.92 56.68,49.62 56.68,43.62 R36.1
N$55
  Bottom 0.3: QG2.8 90.88,9.12 90.88,22.32 91.78,23.22 91.78,37.92 85.48,44.22 J5.2
N$63
  Bottom 0.3: D1.A 93.88,44.82 93.88,45.42 90.28,49.02 90.28,52.02 89.38,52.92 R33.1
N$64
  Bottom 0.3: IC5.14 75.28,47.56 74.09,47.57 73.79,47.57 73.8,51.93 78.87,51.86 R33.2
VCC
  Top 0.3: IC3.14 48.88,68.82 51.29,68.82 54.06,71.54 64.48,71.52 65.78,72.95 79.78,72.95 C14.2 80.68,72.12 85.78,67.02 85.78,49.02 83.98,47.22 83.98,37.92 82.18,36.12 J2.3 82.18,34.92 83.08,33.99 83.07,32.61 83.97,31.74 85.05,31.74 86.68,34.02 86.68,35.52 C16.2 | QG2.14 89.98,23.82 84.58,23.82 77.88,17.09 75.48,17.09 72.88,19.92 70.48,19.92 63.28,12.72 IC1.OUT
  Top 0.61: C18.2 37.78,13.02 31.18,13.02 C17.2
  Bottom 0.3: IC5.16 IC5.15 76.18,46.91 77.98,46.91 80.08,49.02 83.22,49.03 83.15,49.09 83.15,53.32 80.08,56.39 80.08,56.41 80.09,56.42 80.08,63.42 79.78,63.72 79.78,70.62 | 79.78,70.62 79.78,71.82 C14.2 | 79.78,70.62 76.18,70.62 IC4.16 | QG2.14 90.28,24.42 90.28,32.22 86.98,35.52 C16.2 | IC5.4 68.68,45.6 70.2,45.6 79.78,36.12 J2.3 | 41.68,13.02 45.04,13.02 49.54,17.52 R37.2 | 50.98,3.72 C15.2
  Bottom 0.61: C27.+ 14.38,5.82 21.02,5.82 28.52,13.32 30.58,13.32 C17.2 | C18.2 38.68,13.02 41.68,13.02 50.98,3.72 | IC1.OUT 62.22,10.79 57.9,6.72 51.39,6.77 C15.2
